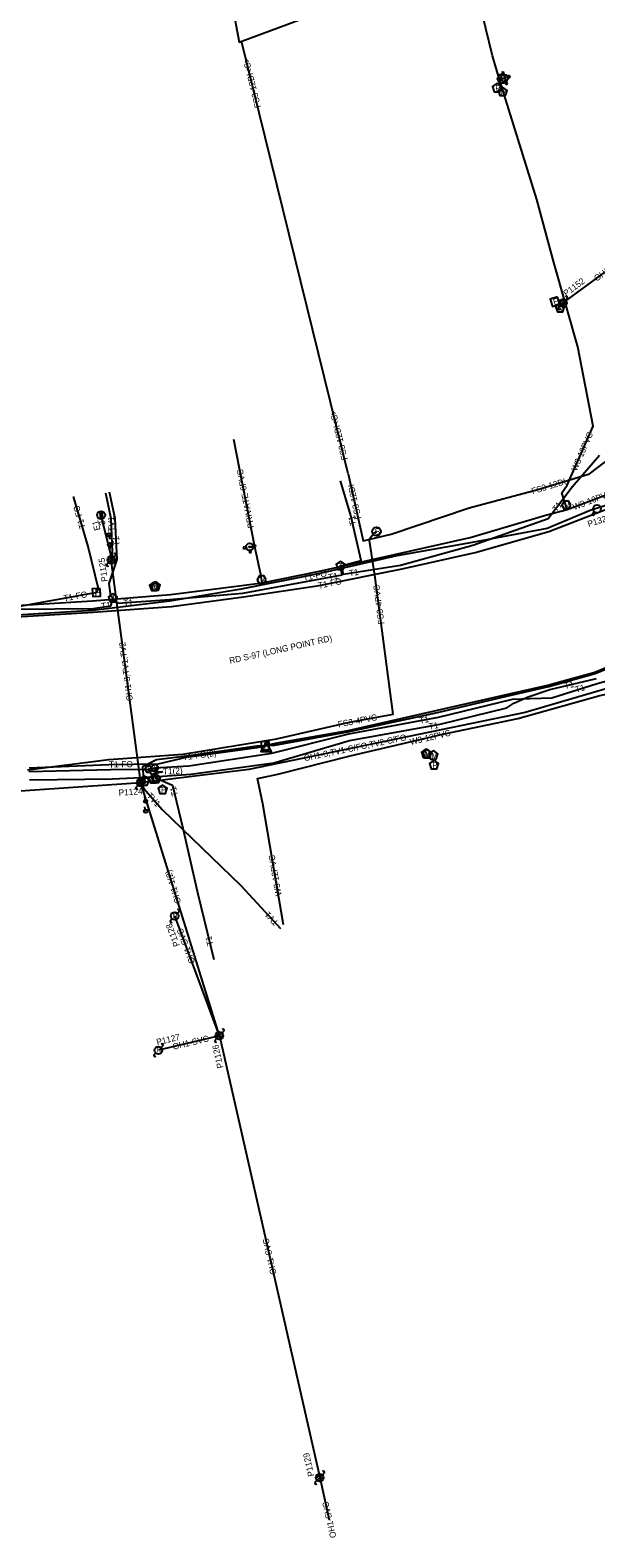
# Model space of a CAD drawing. Extents: x 2336688 to 2352634, y 362473 to 369571.
# Drawn here: x 2346395 to 2346760, y 366579 to 367550 of the extents above; entities that cross this region are included whole.
import ezdxf

# ---------------------------------------------------------------- set-up
doc = ezdxf.new("R2010")
doc.units = 0
for name, color, linetype in [('RD_EX_Bldg_txCode', 7, 'Continuous'), ('RD_EX_DV_Prop', 7, 'Continuous'), ('RD_EX_DV_TX_Prop', 7, 'Continuous'), ('RD_EX_RW', 7, 'Continuous'), ('RD_EX_RW_TX', 7, 'Continuous'), ('RD_HC_Data_Tic', 7, 'Continuous'), ('RD_PD_CstnLmt', 7, 'Continuous'), ('RD_PD_Final_TrvlWay', 7, 'Continuous'), ('RD_PD_PatLn3', 7, 'Continuous'), ('RD_PD_PatLn4', 7, 'Continuous'), ('RD_SHT_ShtClip', 7, 'Continuous'), ('RD_Sketch1', 7, 'Continuous'), ('RD_Sketch2', 7, 'Continuous'), ('RD_Sketch5', 7, 'Continuous'), ('RD_TX_Misc1', 7, 'Continuous')]:
    doc.layers.add(name, color=color, linetype=linetype)

# ---------------------------------------------------------------- blocks, each defined once
blk = doc.blocks.new('GW')
at = {"layer": 'RD_HC_Data_Tic'}
blk.add_line((0, 0), (0, 5), dxfattribs=at)
blk.add_circle((0, 0), 2, dxfattribs=at)

msp = doc.modelspace()

# ---------------------------------------------------------------- linework, layer by layer
at = {"layer": 'RD_EX_Bldg_txCode'}
msp.add_lwpolyline([(2346550.34, 367598.28), (2346520.78, 367589.68), (2346529.42, 367542.62), (2346575.28, 367559.45), (2346565.23, 367602.1), (2346550.34, 367598.28)], dxfattribs=at)
at = {"layer": 'RD_EX_RW'}
for q in [(2346472.89, 367070.63), (2346475.41, 367072.04)]:
    msp.add_line((2346480.28, 367072.36), q, dxfattribs=at)
at = {"layer": 'RD_EX_RW_TX'}
for points in [[(2346386.07, 367172.12), (2346435.22, 367175.26), (2346485.78, 367178.87), (2346532.3, 367185.17), (2346581.16, 367192.44), (2346634.62, 367203.07), (2346681.71, 367213.65), (2346729.26, 367227.27), (2346757.13, 367237.94), (2346775.57, 367244.97), (2346872.31, 367276.87), (2346887.68, 367285.05), (2346890.71, 367286.97), (2346890.49, 367289.26), (2346891.73, 367297.92), (2346894.69, 367301.37)], [(2346385.55, 367177.07), (2346435.32, 367177.69), (2346446.63, 367179.39), (2346447.77, 367182.84), (2346447.98, 367184.28), (2346448.52, 367182.97), (2346451.31, 367180.94), (2346484.58, 367183.45), (2346531.8, 367187.56), (2346581.96, 367196.69), (2346595.9, 367199.33), (2346594.9, 367204.08), (2346594.84, 367205.2), (2346595.56, 367204.23), (2346596.66, 367199.65), (2346633.67, 367205.56), (2346680.3, 367218.5), (2346728.88, 367235.57), (2346744.36, 367255.92), (2346762.03, 367276.39)], [(2346594.84, 367205.2), (2346596.21, 367205.27), (2346608.27, 367208.47), (2346601.65, 367237.47), (2346594.88, 367259.82)], [(2346150.19, 367163.96), (2346152.78, 367164.94), (2346183.57, 367166.86), (2346234.04, 367170.82), (2346281.59, 367173.57), (2346333.01, 367174.76), (2346385.66, 367178.6), (2346433.22, 367187.2), (2346437.38, 367187.88), (2346438.71, 367190.16), (2346431.98, 367217.52), (2346422.54, 367249.73)], [(2346775.81, 367246.88), (2346756.05, 367240.68), (2346728.16, 367229.06), (2346679.88, 367220.09), (2346631.22, 367211.6), (2346581.48, 367200.25), (2346530.76, 367190.1), (2346484.75, 367182.32), (2346435.05, 367176.31), (2346385.93, 367173.28)], [(2346446.97, 367208.91), (2346447.89, 367208.67), (2346446.8, 367235.27), (2346443.46, 367251.96)], [(2346447.98, 367184.28), (2346446.72, 367185.45), (2346445.63, 367193.6), (2346450.71, 367209.13), (2346449.47, 367235.56), (2346445.74, 367252.49)], [(2346393.84, 367072.51), (2346446.37, 367073.84), (2346470.99, 367074.08), (2346475.1, 367074.82), (2346497.02, 367076.2), (2346550.51, 367084.4), (2346600.16, 367096.76), (2346658.08, 367107.59), (2346705.97, 367119.19), (2346717.24, 367119.65), (2346731.3, 367119.99), (2346760.58, 367129.35), (2346804.71, 367141.52), (2346806.24, 367141.63), (2346825.71, 367145.72), (2346849.8, 367151.32), (2346870.64, 367156.98), (2346892.17, 367163.68), (2346898.36, 367165.45), (2346899.77, 367165.87), (2346913.35, 367169.48)], [(2346394.02, 367074.91), (2346445.72, 367076.99), (2346477.17, 367077.53), (2346495.43, 367081.82), (2346541.01, 367087.98), (2346546.37, 367089.19), (2346552.55, 367089.57), (2346599.67, 367098.16), (2346657.49, 367110.63), (2346704.91, 367121.78), (2346729.35, 367127.28), (2346759.16, 367135.67), (2346783.33, 367145.57)], [(2346783.01, 367146.37), (2346758.96, 367136.25), (2346729.29, 367128.08), (2346704.63, 367122.66), (2346657.28, 367111.92), (2346599.58, 367098.8), (2346552.77, 367090.62), (2346546.37, 367089.19), (2346540.83, 367088.86), (2346495.43, 367082.4), (2346476.11, 367080.14), (2346467.2, 367075.59), (2346467.81, 367068.34), (2346468.58, 367066.29)], [(2346394.25, 367067.17), (2346447.78, 367067.91), (2346470.82, 367068.9), (2346498.4, 367070.84), (2346551.97, 367078.06), (2346600.62, 367092.58), (2346659.23, 367103.09), (2346702.17, 367113.48), (2346706.8, 367116.66), (2346715.94, 367120.69), (2346729.92, 367125.44), (2346760.09, 367132.46)], [(2346470.99, 367074.08), (2346474.08, 367068.49), (2346474.13, 367067.6), (2346474.13, 367067.6)], [(2346475.1, 367074.82), (2346475.79, 367068.66), (2346475.83, 367067.99), (2346476.97, 367067.91), (2346486.39, 367063.82), (2346493.11, 367035.93), (2346502.59, 366994.65), (2346513.24, 366951.35)], [(2346465.94, 367065.34), (2346467.88, 367061.62), (2346479.92, 367048.14), (2346530.55, 366999.1), (2346556.25, 366971.3)]]:
    msp.add_lwpolyline(points, dxfattribs=at)
for points in [[(2346594.84, 367208.2), (2346591.99, 367206.13), (2346593.08, 367202.77), (2346596.61, 367202.77), (2346597.7, 367206.13)], [(2346439.74, 367190.52), (2346434.75, 367190.24), (2346435.02, 367185.25), (2346440.02, 367185.52)], [(2346447.98, 367187.28), (2346445.13, 367185.21), (2346446.22, 367181.85), (2346449.75, 367181.85), (2346450.84, 367185.21)], [(2346548.77, 367091.78), (2346543.77, 367091.59), (2346543.96, 367086.59), (2346548.96, 367086.78)], [(2346473.3, 367074.08), (2346472.14, 367076.08), (2346469.83, 367076.08), (2346468.68, 367074.08), (2346469.83, 367072.08), (2346472.14, 367072.08)], [(2346474.13, 367070.6), (2346471.27, 367068.53), (2346472.36, 367065.17), (2346475.89, 367065.17), (2346476.98, 367068.53)], [(2346477.41, 367074.82), (2346476.26, 367076.82), (2346473.95, 367076.82), (2346472.79, 367074.82), (2346473.95, 367072.82), (2346476.26, 367072.82)], [(2346475.83, 367070.99), (2346472.98, 367068.91), (2346474.07, 367065.56), (2346477.6, 367065.56), (2346478.69, 367068.91)], [(2346471.47, 367066.29), (2346470.03, 367068.79), (2346467.14, 367068.79), (2346465.7, 367066.29), (2346467.14, 367063.79), (2346470.03, 367063.79)]]:
    msp.add_lwpolyline(points, close=True, dxfattribs=at)
at = {"layer": 'RD_HC_Data_Tic'}
for p, q in [((2346735.55, 367371.68), (2346736.61, 367372.74)), ((2346735.97, 367373.86), (2346739.03, 367376.93)), ((2346736.61, 367372.74), (2346740.15, 367376.28)), ((2346737.73, 367372.1), (2346740.8, 367375.16)), ((2346740.15, 367376.28), (2346741.21, 367377.34)), ((2346757.61, 367239.01), (2346758.67, 367240.07)), ((2346444.14, 367206.08), (2346445.2, 367207.14)), ((2346444.55, 367208.26), (2346447.61, 367211.32)), ((2346445.2, 367207.14), (2346448.73, 367210.68)), ((2346446.32, 367206.5), (2346449.38, 367209.56)), ((2346448.73, 367210.68), (2346449.8, 367211.74)), ((2346463.11, 367062.51), (2346464.17, 367063.57)), ((2346463.52, 367064.69), (2346466.58, 367067.75)), ((2346464.17, 367063.57), (2346467.7, 367067.1)), ((2346465.29, 367062.92), (2346468.35, 367065.98)), ((2346467.7, 367067.1), (2346468.76, 367068.17)), ((2346489.69, 366981.2), (2346490.75, 366982.27)), ((2346485.1, 366976.61), (2346486.16, 366977.67)), ((2346514.33, 366901.64), (2346517.39, 366904.7)), ((2346514.97, 366900.52), (2346518.51, 366904.06)), ((2346518.51, 366904.06), (2346519.57, 366905.12)), ((2346479.17, 366894.69), (2346480.23, 366895.75)), ((2346513.91, 366899.46), (2346514.97, 366900.52)), ((2346516.09, 366899.87), (2346519.16, 366902.94)), ((2346474.57, 366890.09), (2346475.63, 366891.15)), ((2346578.64, 366614.67), (2346579.7, 366615.74)), ((2346579.05, 366616.86), (2346582.11, 366619.92)), ((2346579.7, 366615.74), (2346583.23, 366619.27)), ((2346580.82, 366615.09), (2346583.88, 366618.15)), ((2346583.23, 366619.27), (2346584.29, 366620.33))]:
    msp.add_line(p, q, dxfattribs=at)
for centre in [(2346738.38, 367374.51), (2346760.44, 367241.84), (2346446.97, 367208.91), (2346465.94, 367065.34), (2346487.92, 366979.44), (2346516.74, 366902.29), (2346477.4, 366892.92), (2346581.47, 366617.5)]:
    msp.add_circle(centre, 2.5, dxfattribs=at)
for centre, start, end in [((2346736.08, 367371.15), 135, 315), ((2346740.68, 367377.87), 315, 135), ((2346758.14, 367238.48), 135, 315), ((2346444.67, 367205.55), 135, 315), ((2346449.27, 367212.27), 315, 135), ((2346468.23, 367068.7), 315, 135), ((2346463.64, 367061.98), 135, 315), ((2346490.22, 366982.8), 315, 135), ((2346485.63, 366976.08), 135, 315), ((2346519.04, 366905.65), 315, 135), ((2346479.7, 366896.28), 315, 135), ((2346514.44, 366898.93), 135, 315), ((2346475.1, 366889.56), 135, 315), ((2346579.17, 366614.14), 135, 315), ((2346583.76, 366620.86), 315, 135)]:
    msp.add_arc(centre, 0.75, start, end, dxfattribs=at)
at = {"layer": 'RD_PD_Final_TrvlWay'}
for points in [[(2346734.97, 367378.39), (2346730.2, 367376.88), (2346731.71, 367372.12), (2346736.47, 367373.62)], [(2346441.11, 367240.17), (2346441.19, 367236.57), (2346440.15, 367238.21), (2346440.27, 367235.28), (2346439.75, 367239.22), (2346440.87, 367237.54)]]:
    msp.add_lwpolyline(points, close=True, dxfattribs=at)
msp.add_lwpolyline([(2346440.41, 367237.78), (2346441.11, 367233.98), (2346446.84, 367211.16), (2346446.97, 367208.91)], dxfattribs=at)
msp.add_circle((2346440.41, 367237.78), 2.55, dxfattribs=at)
at = {"layer": 'RD_PD_PatLn3'}
msp.add_lwpolyline([(2346546.87, 367091.44), (2346543.4, 367085.44), (2346550.33, 367085.44)], close=True, dxfattribs=at)
at = {"layer": 'RD_SHT_ShtClip'}
for p, q in [((2346809.69, 367427.05), (2346738.38, 367374.51)), ((2346465.94, 367065.34), (2346446.97, 367208.91)), ((2346465.94, 367065.34), (2346246.56, 367049.83)), ((2346516.74, 366902.29), (2346465.94, 367065.34)), ((2346516.74, 366902.29), (2346487.92, 366979.44)), ((2346516.74, 366902.29), (2346477.4, 366892.92)), ((2346516.74, 366902.29), (2346581.47, 366617.5)), ((2346581.47, 366617.5), (2346587.67, 366590.2))]:
    msp.add_line(p, q, dxfattribs=at)
msp.add_lwpolyline([(2346781.51, 367130.24), (2346714.11, 367110.5), (2346535.66, 367073.8), (2346465.94, 367065.34)], dxfattribs=at)
at = {"layer": 'RD_Sketch2'}
for p, q in [((2346700.03, 367523.36), (2346698.93, 367523)), ((2346698.93, 367523), (2346699.48, 367521.34)), ((2346700.59, 367521.66), (2346700.03, 367523.36)), ((2346700.9, 367517.05), (2346701.47, 367515.32)), ((2346702.56, 367515.69), (2346701.98, 367517.45)), ((2346704.02, 367521.01), (2346702.63, 367520.55)), ((2346702.96, 367519.45), (2346704.39, 367519.92)), ((2346704.39, 367519.92), (2346704.02, 367521.01)), ((2346701.47, 367515.32), (2346702.56, 367515.69)), ((2346533.91, 367217.43), (2346532.12, 367217.15)), ((2346532.12, 367217.15), (2346532.29, 367216.01)), ((2346532.29, 367216.01), (2346534.13, 367216.29)), ((2346535.94, 367214.99), (2346536.16, 367213.51)), ((2346537.31, 367213.69), (2346537.08, 367215.14)), ((2346540.11, 367218.38), (2346538.37, 367218.11)), ((2346538.51, 367216.96), (2346540.28, 367217.24)), ((2346540.28, 367217.24), (2346540.11, 367218.38)), ((2346536.16, 367213.51), (2346537.31, 367213.69))]:
    msp.add_line(p, q, dxfattribs=at)
for points in [[(2346741.1, 367241.32), (2346737.67, 367252.1), (2346741.22, 367257.03), (2346757.99, 367295.14), (2346748.08, 367346.19), (2346732.63, 367400.55), (2346721.55, 367441.12), (2346697.44, 367518.56), (2346693, 367533.8), (2346684.39, 367569.05), (2346661.25, 367635.9), (2346649.68, 367679.89), (2346635.8, 367728.93), (2346621.54, 367774.47), (2346588.43, 367887.35), (2346563.64, 367964.78), (2346538.6, 368055.07), (2346489.45, 368242.94), (2346465.74, 368320.9), (2346439.88, 368398.73), (2346429.38, 368455.01), (2346416.61, 368524.92)], [(2346697.44, 367518.56), (2346699.84, 367519.34), (2346700.66, 367519.35)], [(2346386.09, 367179.42), (2346434.89, 367182.46), (2346485.2, 367186.56), (2346529.45, 367192.27), (2346544.39, 367194.22), (2346581.43, 367201.55), (2346629.82, 367212.48), (2346678.58, 367223.4), (2346728.01, 367238.02), (2346741.1, 367241.32), (2346773.19, 367253.5), (2346821.4, 367269.08), (2346868.26, 367284.43), (2346876.19, 367287.27), (2346880.2, 367288.69)], [(2346544.39, 367194.22), (2346543.45, 367199.55), (2346539.54, 367217.35), (2346526.12, 367286.51)], [(2346536.22, 367217.28), (2346538.04, 367217.41), (2346539.48, 367217.67)], [(2346558.16, 366973.72), (2346544.75, 367051.67), (2346541.37, 367068.09), (2346554.4, 367070.88), (2346601.18, 367082.55), (2346661, 367096.52), (2346709.36, 367106.7), (2346762.15, 367121.42), (2346778.82, 367125.01), (2346800.35, 367132.17), (2346795.56, 367149.03), (2346820.27, 367156.57), (2346846.65, 367164.22), (2346872.89, 367172.24), (2346874.94, 367172.89)]]:
    msp.add_lwpolyline(points, dxfattribs=at)
for points in [[(2346695.88, 367516.14), (2346692.98, 367514.04), (2346694.09, 367510.63), (2346697.67, 367510.63), (2346698.78, 367514.04)], [(2346701.7, 367518.95), (2346700.25, 367521.45), (2346697.37, 367521.45), (2346695.92, 367518.95), (2346697.37, 367516.45), (2346700.25, 367516.45)], [(2346699.49, 367513.61), (2346696.58, 367511.5), (2346697.69, 367508.09), (2346701.28, 367508.09), (2346702.39, 367511.5)], [(2346736.6, 367374.34), (2346733.7, 367372.23), (2346734.8, 367368.82), (2346738.39, 367368.82), (2346739.5, 367372.23)], [(2346743.43, 367244.24), (2346741.99, 367246.74), (2346739.1, 367246.74), (2346737.66, 367244.24), (2346739.1, 367241.74), (2346741.99, 367241.74)], [(2346546.91, 367196.04), (2346545.47, 367198.54), (2346542.58, 367198.54), (2346541.14, 367196.04), (2346542.58, 367193.54), (2346545.47, 367193.54)], [(2346474.64, 367194.78), (2346471.74, 367192.67), (2346472.85, 367189.26), (2346476.43, 367189.26), (2346477.54, 367192.67)], [(2346475.67, 367194.89), (2346472.77, 367192.78), (2346473.88, 367189.37), (2346477.47, 367189.37), (2346478.57, 367192.78)], [(2346650.1, 367087.07), (2346647.19, 367084.96), (2346648.3, 367081.55), (2346651.89, 367081.55), (2346653, 367084.96)], [(2346650.77, 367086.87), (2346647.87, 367084.76), (2346648.98, 367081.35), (2346652.56, 367081.35), (2346653.67, 367084.76)], [(2346654.81, 367086.06), (2346651.91, 367083.96), (2346653.02, 367080.55), (2346656.6, 367080.55), (2346657.71, 367083.96)], [(2346655.23, 367079.78), (2346652.33, 367077.67), (2346653.44, 367074.26), (2346657.02, 367074.26), (2346658.13, 367077.67)], [(2346480.16, 367063.81), (2346477.26, 367061.71), (2346478.37, 367058.3), (2346481.95, 367058.3), (2346483.06, 367061.71)]]:
    msp.add_lwpolyline(points, close=True, dxfattribs=at)
for centre, radius in [((2346700.66, 367519.35), 2.31), ((2346700.66, 367519.35), 0.289), ((2346536.22, 367217.28), 2.31), ((2346536.22, 367217.28), 0.289)]:
    msp.add_circle(centre, radius, dxfattribs=at)
for centre, start, end in [((2346700.66, 367519.35), 91.60125, 120.57757), ((2346700.66, 367519.35), 275.94754, 304.92386), ((2346700.66, 367519.35), 2.50808, 31.47532), ((2346536.22, 367217.28), 176.43653, 205.41285), ((2346536.22, 367217.28), 262.99707, 291.96431), ((2346536.22, 367217.28), 352.09025, 21.06657)]:
    msp.add_arc(centre, 2.31, start, end, dxfattribs=at)
at = {"layer": 'RD_Sketch5'}
msp.add_line((2346599.88, 367264.44), (2346531.07, 367543.22), dxfattribs=at)
for points in [[(2346599.88, 367264.44), (2346605.93, 367237.48), (2346609.58, 367221.28), (2346627.52, 367225.39), (2346678, 367242.45), (2346722.14, 367254.26), (2346755.51, 367264.46), (2346765.39, 367271.81), (2346766.84, 367273.09)], [(2346392.92, 367073.62), (2346445.33, 367080.3), (2346493.11, 367083.74), (2346553.58, 367093.67), (2346600.62, 367104.37), (2346627.75, 367109.32), (2346628.94, 367109.45), (2346626.73, 367125.71), (2346617.36, 367197.51), (2346613.7, 367221.44), (2346613.52, 367222.45), (2346616.62, 367226.26), (2346618.14, 367227.26)]]:
    msp.add_lwpolyline(points, dxfattribs=at)
msp.add_circle((2346618.14, 367227.26), 2.75, dxfattribs=at)

# ---------------------------------------------------------------- block references
at = {"layer": 'RD_HC_Data_Tic', "yscale": 0.5546771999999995}
for p, xscale, rotation in [((2346445.45, 367225.08), 0.5546771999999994, -174.27514591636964), ((2346445.81, 367218.86), 0.5546771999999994, -174.27514591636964), ((2346469.12, 367053.36), 0.5546771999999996, 11.686470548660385), ((2346469.15, 367046.96), 0.5546771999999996, 11.686470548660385)]:
    msp.add_blockref('GW', p, dxfattribs=dict(at, xscale=xscale, rotation=rotation))

# ---------------------------------------------------------------- texts
at = {"layer": 'RD_EX_DV_Prop'}
for s, p in [('E1', (2346440.03, 367228.35)), ('-3', (2346443.77, 367230.03))]:
    msp.add_text(s, height=4, rotation=104.09473, dxfattribs=at).set_placement(p)
at = {"layer": 'RD_EX_DV_TX_Prop'}
for s, rotation, p in [('P1152', 36.38199, (2346740.53, 367378.54)), ('P1322', 17.91183, (2346755.04, 367229.99)), ('P1125', 97.52599, (2346444.69, 367195.11)), ('P1124', 4.04222, (2346451.85, 367056.86)), ('P1128', 110.48276, (2346491.22, 366960.52)), ('P1127', 13.39296, (2346476.62, 366896.15)), ('P1126', 102.80425, (2346519.35, 366881.77)), ('P1129', 102.80425, (2346577.96, 366618.7))]:
    msp.add_text(s, height=4, rotation=rotation, dxfattribs=at).set_placement(p)
at = {"layer": 'RD_EX_RW'}
for s, rotation, p in [('T1', 52.75054, (2346734.36, 367239.47)), ('T1-FO', 106.33472, (2346430.52, 367229.62)), ('TV1', 92.33792, (2346449.16, 367227.2)), ('T1', 102.86497, (2346605.05, 367231.55)), ('T1', 92.69459, (2346452.29, 367218.07)), ('T1-FO', 11.25242, (2346571.2, 367195.39)), ('T1-FO', 11.25242, (2346580.83, 367190.33)), ('T1', 10.71119, (2346587.42, 367195.69)), ('T1', 9.06673, (2346600.73, 367198.27)), ('T1-FO', 10.25141, (2346416.55, 367182.15)), ('T1', 8.54141, (2346440.83, 367177.13)), ('T1', 4.31561, (2346454.99, 367179.21)), ('T1', 13.07987, (2346739.78, 367125.62)), ('T1', 17.72706, (2346747.06, 367123.25)), ('T1', 10.59803, (2346646.12, 367103.32)), ('T1', 10.16189, (2346652.24, 367099.52)), ('T1-FO', 0.98741, (2346445.52, 367075.06)), ('T1-FO(2)', 7.69071, (2346493.29, 367079.68)), ('T1(2)', 4.01726, (2346480.42, 367070.37)), ('T1', 103.54204, (2346490.06, 367057.14)), ('TV1', 311.76309, (2346469.63, 367056.66)), ('TV1', 132.75336, (2346555.17, 366975.42)), ('T1', 103.82527, (2346512.98, 366960.77))]:
    msp.add_text(s, height=4, rotation=rotation, dxfattribs=at).set_placement(p)
at = {"layer": 'RD_EX_RW_TX'}
for s, height, p in [('T', 3.75, (2346593.61, 367202.97)), ('T', 3.75, (2346446.75, 367182.05)), ('X', 3, (2346470.04, 367072.58)), ('X', 3, (2346474.16, 367073.32)), ('T', 3.75, (2346474.61, 367065.76)), ('T', 3.75, (2346467.37, 367064.42)), ('T', 3.75, (2346472.9, 367065.37))]:
    msp.add_text(s, height=height, dxfattribs=at).set_placement(p)
for rotation, p in [(3.18182, (2346436.36, 367185.82)), (2.17061, (2346545.31, 367087.15))]:
    msp.add_text('F', height=4, rotation=rotation, dxfattribs=at).set_placement(p)
at = {"layer": 'RD_HC_Data_Tic'}
for p in [(2346486.74, 366978.11), (2346476.22, 366891.59)]:
    msp.add_text('m', height=4, rotation=360, dxfattribs=at).set_placement(p)
at = {"layer": 'RD_PD_CstnLmt'}
for s, rotation, p in [('W3-10PVC', 66.24023, (2346747.24, 367265.76)), ('PRIVATE-6PVC', 100.98409, (2346539.18, 367229.73)), ('W3-10PVC', 20.78248, (2346745.68, 367240.92)), ('W3-12PVC', 13.14765, (2346640.2, 367089.61)), ('W3-12PVC', 99.76289, (2346556.92, 366992.73))]:
    msp.add_text(s, height=4, rotation=rotation, dxfattribs=at).set_placement(p)
at = {"layer": 'RD_PD_Final_TrvlWay'}
msp.add_text('E', height=4, rotation=17.53586, dxfattribs=at).set_placement((2346732.78, 367372.98))
at = {"layer": 'RD_PD_PatLn3'}
msp.add_text('U', height=2.4, dxfattribs=at).set_placement((2346546.11, 367086.24))
at = {"layer": 'RD_PD_PatLn4'}
for s, rotation, p in [('OH1-3/SVC,T1-FO,T2-FO,T4-FO,TV1-C/FO,TV2-C/FO', 106.1679, (2346792.16, 367495.05)), ('OH1-SVC', 36.38199, (2346760.24, 367388.13)), ('OH1-3,TV1,TV2', 97.52599, (2346460.97, 367118.2)), ('OH1-3,TV1-C/FO,TV2-C/FO', 11.62131, (2346571.69, 367079.17)), ('OH1-1(2)', 107.30743, (2346492.09, 366988.11)), ('OH1-SVC', 110.48276, (2346501.2, 366949.6)), ('OH1-SVC', 13.39296, (2346487.11, 366893.18)), ('OH1-SVC', 102.80425, (2346553.68, 366748.8)), ('OH1-SVC', 102.80425, (2346592.24, 366579.11))]:
    msp.add_text(s, height=4, rotation=rotation, dxfattribs=at).set_placement(p)
at = {"layer": 'RD_Sketch1'}
for s, rotation, p in [('FS3-12DI<C>', 103.86507, (2346543.61, 367500.77)), ('FS3-12DI<C>', 103.86507, (2346599.62, 367273.83)), ('FS3-12DI', 102.6642, (2346608.4, 367235.61)), ('FS3-12DI', 16.99082, (2346718.81, 367251.15)), ('FS3-4PVC', 97.4338, (2346623.27, 367167.69)), ('FS3-4PVC', 10.62603, (2346593.63, 367100.94))]:
    msp.add_text(s, height=4, rotation=rotation, dxfattribs=at).set_placement(p)
at = {"layer": 'RD_Sketch2'}
for s, p in [('V', (2346697.6, 367517.07)), ('M', (2346698.12, 367508.56)), ('M', (2346735.23, 367369.3)), ('V', (2346739.33, 367242.36)), ('V', (2346542.82, 367194.16)), ('M', (2346473.27, 367189.73)), ('M', (2346474.3, 367189.85)), ('M', (2346648.73, 367082.02)), ('M', (2346649.4, 367081.83)), ('M', (2346653.44, 367081.02))]:
    msp.add_text(s, height=3.75, dxfattribs=at).set_placement(p)
for p in [(2346694.73, 367511.22), (2346654.08, 367074.85), (2346479.01, 367058.89)]:
    msp.add_text('P', height=3.75, rotation=360, dxfattribs=at).set_placement(p)
at = {"layer": 'RD_Sketch5'}
msp.add_text('S', height=3.93, dxfattribs=at).set_placement((2346616.93, 367225.3))
at = {"layer": 'RD_TX_Misc1'}
msp.add_text('RD S-97 (LONG POINT RD)', height=4, rotation=12.5991, dxfattribs=at).set_placement((2346523.63, 367141.91))

doc.saveas('drawing.dxf')
